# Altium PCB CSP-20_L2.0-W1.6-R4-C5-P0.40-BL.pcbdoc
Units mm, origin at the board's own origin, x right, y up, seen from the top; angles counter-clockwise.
Board outline 14.85 x 14.9 mm, 2 copper layers (Top Layer, Bottom Layer), stack 0 mm thick; 1 components, 0 nets, 20 pads, 0 vias.
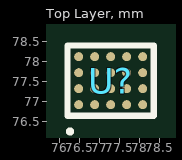
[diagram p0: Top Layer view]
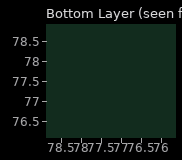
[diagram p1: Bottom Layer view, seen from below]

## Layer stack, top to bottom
Top Layer: signal copper (thickness not stored)
Bottom Layer: signal copper (thickness not stored)

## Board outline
84.702,69.85 69.85,69.85 69.85,84.746 84.702,84.746

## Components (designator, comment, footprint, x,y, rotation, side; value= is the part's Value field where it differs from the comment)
U? "" CSP-20_L2.0-W1.6-R4-C5-P0.40-BL 77.276,77.52 r0 top

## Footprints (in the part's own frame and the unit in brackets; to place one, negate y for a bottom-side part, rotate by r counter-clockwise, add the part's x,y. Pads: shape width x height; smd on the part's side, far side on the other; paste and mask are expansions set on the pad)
CSP-20_L2.0-W1.6-R4-C5-P0.40-BL [mil]
  round 8.82 smd paste-3937 mask+2: A1(-31.5,-23.62) A2(-31.5,-7.87) A3(-31.5,7.87) A4(-31.5,23.62) B1(-15.75,-23.62) B2(-15.75,-7.87) B3(-15.75,7.87) B4(-15.75,23.62) C1(0,-23.62) C2(0,-7.87) C3(0,7.87) C4(0,23.62) D1(15.75,-23.62) D2(15.75,-7.87) D3(15.75,7.87) D4(15.75,23.62) E1(31.5,-23.62) E2(31.5,-7.87) E3(31.5,7.87) E4(31.5,23.62)
  silkscreen extent -42,-52 42,34

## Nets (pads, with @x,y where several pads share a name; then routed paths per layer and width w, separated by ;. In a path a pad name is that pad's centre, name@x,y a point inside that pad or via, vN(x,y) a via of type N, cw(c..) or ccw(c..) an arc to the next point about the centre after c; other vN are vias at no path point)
pads on no net: U?.A1 U?.A2 U?.A3 U?.A4 U?.B1 U?.B2 U?.B3 U?.B4 U?.C1 U?.C2 U?.C3 U?.C4 U?.D1 U?.D2 U?.D3 U?.D4 U?.E1 U?.E2 U?.E3 U?.E4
